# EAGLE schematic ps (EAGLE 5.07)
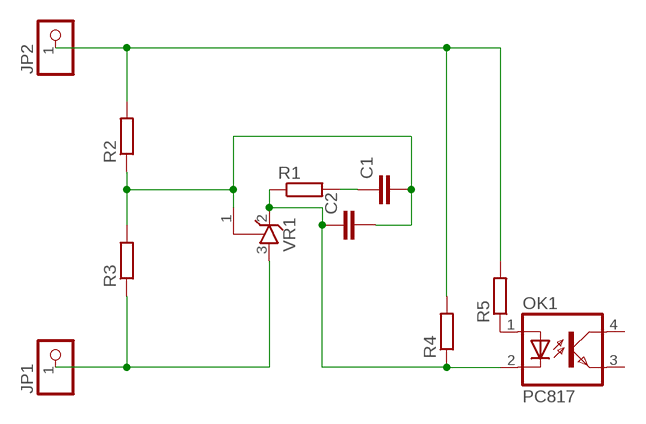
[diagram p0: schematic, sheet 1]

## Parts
C1  C-EUC0805  [C0805]
C2  C-EUC0805  [C0805]
JP1  PINHD-1X11X0.4  [1X01]
JP2  PINHD-1X11X0.4  [1X01]
OK1  PC817  [DIL04]
R1  R-EU_R0805  [R0805]
R2  R-EU_R0805  [R0805]
R3  R-EU_R0805  [R0805]
R4  R-EU_R0805  [R0805]
R5  R-EU_R0805  [R0805]
VR1  TL431CLPSOT23  [SOT23]

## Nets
N$1: JP1.1 R3.1 VR1.3(A)
N$2: C1.2 C2.2 R2.1 R3.2 VR1.1(R)
N$3: C1.1 R1.2
N$5: JP2.1 R2.2 R4.2 R5.2
N$6: C2.1 OK1.2(C) R1.1 R4.1 VR1.2(C)
N$7: OK1.1(A) R5.1
Unconnected: OK1.3(EMIT) OK1.4(COL)

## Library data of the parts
C1 C2 = rcl:C-EU: CAPACITOR, European symbol
JP1 JP2 = pinhead:PINHD-1X1: PIN HEADER
OK1 = optocoupler:PC817: SHARP OPTO COUPLER
R1-R5 = rcl:R-EU_: RESISTOR, European symbol
VR1 = v-reg:TL431CLP: VOLTAGE REGULATOR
